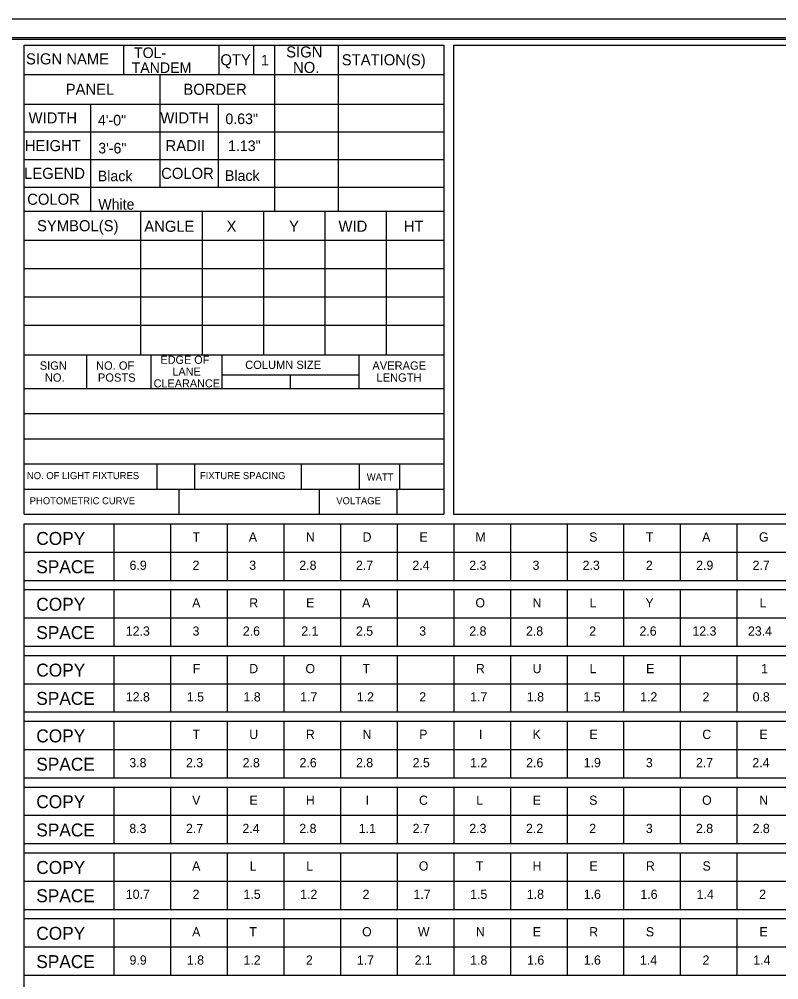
# Model space of a CAD drawing. Extents: x 17890071 to 17890754, y 17897628 to 17897992.
# Drawn here: x 17890152.1 to 17890192.5, y 17897819.5 to 17897870.5 of the extents above; entities that cross this region are included whole.
import ezdxf

# ---------------------------------------------------------------- set-up
doc = ezdxf.new("R2010")
doc.units = 0
for name, color, linetype in [('GSSign', 7, 'Continuous'), ('PlotBorder_dp', 7, 'Continuous'), ('SheetBorder_dp', 7, 'Continuous'), ('SheetLinesMisc1_dp', 7, 'Continuous'), ('SheetLinesMisc2_dp', 7, 'Continuous'), ('TextMinor', 7, 'Continuous')]:
    doc.layers.add(name, color=color, linetype=linetype)

msp = doc.modelspace()

# ---------------------------------------------------------------- linework, layer by layer
at = {"layer": 'PlotBorder_dp'}
msp.add_lwpolyline([(17890071.13, 17897766.734), (17890232.646, 17897766.734), (17890232.646, 17897870.495), (17890071.13, 17897870.495)], close=True, dxfattribs=at)
at = {"layer": 'SheetBorder_dp'}
msp.add_line((17890076.514, 17897869.516), (17890227.262, 17897869.516), dxfattribs=at)
at = {"layer": 'SheetLinesMisc1_dp'}
for p, q in [((17890157.678, 17897867.555), (17890157.678, 17897869.124)), ((17890162.725, 17897869.124), (17890162.725, 17897867.555)), ((17890164.578, 17897869.124), (17890164.578, 17897867.555)), ((17890165.682, 17897869.124), (17890165.682, 17897860.289)), ((17890169.077, 17897869.124), (17890169.077, 17897860.289)), ((17890152.384, 17897867.555), (17890174.695, 17897867.555)), ((17890159.594, 17897867.555), (17890159.594, 17897861.554)), ((17890152.384, 17897865.987), (17890174.695, 17897865.987)), ((17890155.91, 17897865.987), (17890155.91, 17897860.289)), ((17890162.706, 17897865.971), (17890162.706, 17897861.554)), ((17890152.384, 17897864.514), (17890174.695, 17897864.514)), ((17890152.384, 17897863.042), (17890174.695, 17897863.042)), ((17890152.384, 17897861.569), (17890174.695, 17897861.569)), ((17890152.384, 17897860.289), (17890174.695, 17897860.289)), ((17890158.58, 17897860.289), (17890158.58, 17897852.67)), ((17890161.84, 17897860.289), (17890161.84, 17897852.67)), ((17890165.1, 17897860.289), (17890165.1, 17897852.67)), ((17890168.36, 17897860.26), (17890168.36, 17897852.67)), ((17890171.62, 17897860.26), (17890171.62, 17897852.67)), ((17890152.389, 17897858.756), (17890174.695, 17897858.756)), ((17890152.389, 17897857.253), (17890174.695, 17897857.253)), ((17890152.389, 17897855.75), (17890174.695, 17897855.75)), ((17890152.389, 17897854.246), (17890174.695, 17897854.246)), ((17890152.384, 17897852.67), (17890174.695, 17897852.67)), ((17890155.694, 17897852.67), (17890155.694, 17897850.874)), ((17890159.117, 17897852.67), (17890159.117, 17897850.874)), ((17890162.895, 17897852.67), (17890162.895, 17897850.874)), ((17890170.171, 17897852.67), (17890170.171, 17897850.874)), ((17890162.895, 17897851.593), (17890170.166, 17897851.593)), ((17890166.53, 17897851.593), (17890166.53, 17897850.874)), ((17890152.384, 17897850.874), (17890174.694, 17897850.874)), ((17890152.384, 17897849.538), (17890174.694, 17897849.538)), ((17890152.384, 17897848.203), (17890174.695, 17897848.203)), ((17890152.384, 17897846.867), (17890174.695, 17897846.867)), ((17890152.384, 17897845.531), (17890174.695, 17897845.531)), ((17890157.148, 17897843.684), (17890157.148, 17897840.678)), ((17890160.159, 17897843.684), (17890160.159, 17897840.678)), ((17890163.169, 17897843.684), (17890163.169, 17897840.678)), ((17890166.179, 17897843.684), (17890166.179, 17897840.678)), ((17890169.19, 17897843.684), (17890169.19, 17897840.678)), ((17890172.2, 17897843.684), (17890172.2, 17897840.678)), ((17890175.211, 17897843.684), (17890175.211, 17897840.678)), ((17890178.221, 17897843.684), (17890178.221, 17897840.678)), ((17890181.231, 17897843.684), (17890181.231, 17897840.678)), ((17890184.241, 17897843.684), (17890184.241, 17897840.678)), ((17890187.252, 17897843.684), (17890187.252, 17897840.678)), ((17890190.262, 17897843.684), (17890190.262, 17897840.678)), ((17890152.385, 17897842.181), (17890226.387, 17897842.182)), ((17890152.385, 17897840.678), (17890226.387, 17897840.678)), ((17890152.385, 17897840.188), (17890226.387, 17897840.188)), ((17890157.148, 17897840.188), (17890157.148, 17897837.182)), ((17890160.159, 17897840.188), (17890160.159, 17897837.182)), ((17890163.169, 17897840.188), (17890163.169, 17897837.182)), ((17890166.179, 17897840.188), (17890166.179, 17897837.182)), ((17890169.19, 17897840.188), (17890169.19, 17897837.182)), ((17890172.2, 17897840.188), (17890172.2, 17897837.182)), ((17890175.211, 17897840.188), (17890175.211, 17897837.182)), ((17890178.221, 17897840.188), (17890178.221, 17897837.182)), ((17890181.231, 17897840.188), (17890181.231, 17897837.182)), ((17890184.241, 17897840.188), (17890184.241, 17897837.182)), ((17890187.252, 17897840.188), (17890187.252, 17897837.182)), ((17890190.262, 17897840.188), (17890190.262, 17897837.182)), ((17890152.385, 17897838.685), (17890226.387, 17897838.685)), ((17890152.385, 17897837.182), (17890226.387, 17897837.182)), ((17890152.385, 17897836.691), (17890226.387, 17897836.691)), ((17890157.148, 17897836.691), (17890157.148, 17897833.685)), ((17890160.159, 17897836.691), (17890160.159, 17897833.685)), ((17890163.169, 17897836.691), (17890163.169, 17897833.685)), ((17890166.179, 17897836.691), (17890166.179, 17897833.685)), ((17890169.19, 17897836.691), (17890169.19, 17897833.685)), ((17890172.2, 17897836.691), (17890172.2, 17897833.685)), ((17890175.211, 17897836.691), (17890175.211, 17897833.685)), ((17890178.221, 17897836.691), (17890178.221, 17897833.685)), ((17890181.231, 17897836.691), (17890181.231, 17897833.685)), ((17890184.241, 17897836.691), (17890184.241, 17897833.685)), ((17890187.252, 17897836.691), (17890187.252, 17897833.685)), ((17890190.262, 17897836.691), (17890190.262, 17897833.685)), ((17890152.385, 17897835.188), (17890226.387, 17897835.188)), ((17890152.385, 17897833.685), (17890226.387, 17897833.685)), ((17890152.385, 17897833.194), (17890226.387, 17897833.194)), ((17890157.148, 17897833.194), (17890157.148, 17897830.188)), ((17890160.159, 17897833.194), (17890160.159, 17897830.188)), ((17890163.169, 17897833.194), (17890163.169, 17897830.188)), ((17890166.179, 17897833.194), (17890166.179, 17897830.188)), ((17890169.19, 17897833.194), (17890169.19, 17897830.188)), ((17890172.2, 17897833.194), (17890172.2, 17897830.188)), ((17890175.211, 17897833.194), (17890175.211, 17897830.188)), ((17890178.221, 17897833.194), (17890178.221, 17897830.188)), ((17890181.231, 17897833.194), (17890181.231, 17897830.188)), ((17890184.241, 17897833.194), (17890184.241, 17897830.188)), ((17890187.252, 17897833.194), (17890187.252, 17897830.188)), ((17890190.262, 17897833.194), (17890190.262, 17897830.188)), ((17890152.385, 17897831.692), (17890226.387, 17897831.692)), ((17890152.385, 17897830.188), (17890226.387, 17897830.188)), ((17890152.385, 17897829.698), (17890226.387, 17897829.698)), ((17890157.148, 17897829.698), (17890157.148, 17897826.692)), ((17890160.159, 17897829.698), (17890160.159, 17897826.692)), ((17890163.169, 17897829.698), (17890163.169, 17897826.692)), ((17890166.179, 17897829.698), (17890166.179, 17897826.692)), ((17890169.19, 17897829.698), (17890169.19, 17897826.692)), ((17890172.2, 17897829.698), (17890172.2, 17897826.692)), ((17890175.211, 17897829.698), (17890175.211, 17897826.692)), ((17890178.221, 17897829.698), (17890178.221, 17897826.692)), ((17890181.231, 17897829.698), (17890181.231, 17897826.692)), ((17890184.241, 17897829.698), (17890184.241, 17897826.692)), ((17890187.252, 17897829.698), (17890187.252, 17897826.692)), ((17890190.262, 17897829.698), (17890190.262, 17897826.692)), ((17890152.385, 17897828.195), (17890226.387, 17897828.195)), ((17890152.385, 17897826.692), (17890226.387, 17897826.692)), ((17890152.385, 17897826.202), (17890226.387, 17897826.202)), ((17890157.148, 17897826.202), (17890157.148, 17897823.196)), ((17890160.159, 17897826.202), (17890160.159, 17897823.196)), ((17890163.169, 17897826.202), (17890163.169, 17897823.196)), ((17890166.179, 17897826.202), (17890166.179, 17897823.196)), ((17890169.19, 17897826.202), (17890169.19, 17897823.196)), ((17890172.2, 17897826.202), (17890172.2, 17897823.196)), ((17890175.211, 17897826.202), (17890175.211, 17897823.196)), ((17890178.221, 17897826.202), (17890178.221, 17897823.196)), ((17890181.231, 17897826.202), (17890181.231, 17897823.196)), ((17890184.241, 17897826.202), (17890184.241, 17897823.196)), ((17890187.252, 17897826.202), (17890187.252, 17897823.196)), ((17890190.262, 17897826.202), (17890190.262, 17897823.196)), ((17890152.385, 17897824.698), (17890226.387, 17897824.699)), ((17890152.385, 17897823.196), (17890226.387, 17897823.196)), ((17890152.385, 17897822.705), (17890226.387, 17897822.705)), ((17890157.148, 17897822.705), (17890157.148, 17897819.699)), ((17890160.159, 17897822.705), (17890160.159, 17897819.699)), ((17890163.169, 17897822.705), (17890163.169, 17897819.699)), ((17890166.179, 17897822.705), (17890166.179, 17897819.699)), ((17890169.19, 17897822.705), (17890169.19, 17897819.699)), ((17890172.2, 17897822.705), (17890172.2, 17897819.699)), ((17890175.211, 17897822.705), (17890175.211, 17897819.699)), ((17890178.221, 17897822.705), (17890178.221, 17897819.699)), ((17890181.231, 17897822.705), (17890181.231, 17897819.699)), ((17890184.241, 17897822.705), (17890184.241, 17897819.699)), ((17890187.252, 17897822.705), (17890187.252, 17897819.699)), ((17890190.262, 17897822.705), (17890190.262, 17897819.699)), ((17890152.385, 17897821.202), (17890226.387, 17897821.202)), ((17890152.385, 17897819.699), (17890226.387, 17897819.699))]:
    msp.add_line(p, q, dxfattribs=at)
at = {"layer": 'SheetLinesMisc2_dp'}
for p, q in [((17890076.643, 17897869.435), (17890227.099, 17897869.435)), ((17890152.384, 17897869.124), (17890174.695, 17897869.124)), ((17890152.384, 17897844.196), (17890152.384, 17897869.124)), ((17890152.384, 17897869.124), (17890174.695, 17897869.124)), ((17890174.695, 17897869.124), (17890174.695, 17897844.196)), ((17890175.208, 17897869.124), (17890226.38, 17897869.124)), ((17890175.208, 17897869.124), (17890175.208, 17897844.198)), ((17890152.384, 17897846.866), (17890174.69, 17897846.866)), ((17890159.442, 17897846.866), (17890159.442, 17897845.531)), ((17890161.435, 17897846.866), (17890161.435, 17897845.531)), ((17890167.11, 17897846.866), (17890167.11, 17897845.531)), ((17890170.196, 17897846.866), (17890170.196, 17897845.531)), ((17890172.326, 17897846.866), (17890172.326, 17897845.531)), ((17890152.384, 17897845.531), (17890174.69, 17897845.531)), ((17890160.612, 17897845.531), (17890160.612, 17897844.196)), ((17890168.055, 17897845.531), (17890168.055, 17897844.196)), ((17890172.196, 17897845.531), (17890172.196, 17897844.196)), ((17890152.384, 17897844.196), (17890174.69, 17897844.196)), ((17890152.384, 17897844.196), (17890174.695, 17897844.196)), ((17890175.208, 17897844.198), (17890226.38, 17897844.198)), ((17890152.385, 17897823.197), (17890152.385, 17897843.684)), ((17890152.385, 17897843.684), (17890226.387, 17897843.684)), ((17890152.385, 17897776.142), (17890152.385, 17897843.684))]:
    msp.add_line(p, q, dxfattribs=at)

# ---------------------------------------------------------------- texts
at = {"layer": 'GSSign'}
for s, height, p in [('TOL-', 0.5624, (17890158.225, 17897868.433)), ('1', 0.562, (17890164.974, 17897868.039)), ('TANDEM', 0.5624, (17890158.1, 17897867.637)), ('4\'-0"', 0.5624, (17890156.309, 17897864.848)), ('0.63"', 0.5624, (17890163.082, 17897864.922)), ('3\'-6"', 0.5624, (17890156.325, 17897863.363)), ('1.13"', 0.5624, (17890163.222, 17897863.488)), ('Black', 0.5624, (17890156.303, 17897861.883)), ('Black', 0.5624, (17890163.059, 17897861.904)), ('White', 0.5624, (17890156.328, 17897860.379)), ('T', 0.49, (17890161.338, 17897842.739)), ('A', 0.49, (17890164.325, 17897842.739)), ('N', 0.49, (17890167.359, 17897842.739)), ('D', 0.49, (17890170.37, 17897842.739)), ('E', 0.49, (17890173.392, 17897842.739)), ('M', 0.49, (17890176.367, 17897842.739)), ('S', 0.49, (17890182.411, 17897842.739)), ('T', 0.49, (17890185.421, 17897842.739)), ('A', 0.49, (17890188.408, 17897842.739)), ('G', 0.49, (17890191.43, 17897842.739)), ('6.9', 0.4902, (17890157.99, 17897841.236)), ('2', 0.49, (17890161.338, 17897841.236)), ('3', 0.49, (17890164.349, 17897841.236)), ('2.8', 0.4902, (17890167.009, 17897841.236)), ('2.7', 0.4902, (17890170.019, 17897841.236)), ('2.4', 0.4902, (17890173.018, 17897841.236)), ('2.3', 0.4902, (17890176.04, 17897841.236)), ('3', 0.49, (17890179.401, 17897841.236)), ('2.3', 0.4902, (17890182.061, 17897841.236)), ('2', 0.49, (17890185.421, 17897841.236)), ('2.9', 0.4902, (17890188.093, 17897841.236)), ('2.7', 0.4902, (17890191.092, 17897841.236)), ('A', 0.49, (17890161.315, 17897839.242)), ('R', 0.49, (17890164.349, 17897839.242)), ('E', 0.49, (17890167.371, 17897839.242)), ('A', 0.49, (17890170.346, 17897839.242)), ('O', 0.49, (17890176.367, 17897839.242)), ('N', 0.49, (17890179.401, 17897839.242)), ('L', 0.49, (17890182.434, 17897839.242)), ('Y', 0.49, (17890185.398, 17897839.242)), ('L', 0.49, (17890191.465, 17897839.242)), ('12.3', 0.4902, (17890157.791, 17897837.739)), ('3', 0.49, (17890161.338, 17897837.739)), ('2.6', 0.4902, (17890164.01, 17897837.739)), ('2.1', 0.4902, (17890167.114, 17897837.739)), ('2.5', 0.4902, (17890170.019, 17897837.739)), ('3', 0.49, (17890173.38, 17897837.739)), ('2.8', 0.4902, (17890176.04, 17897837.739)), ('2.8', 0.4902, (17890179.051, 17897837.739)), ('2', 0.49, (17890182.411, 17897837.739)), ('2.6', 0.4902, (17890185.083, 17897837.739)), ('12.3', 0.4902, (17890187.895, 17897837.739)), ('23.4', 0.4902, (17890190.847, 17897837.739)), ('F', 0.49, (17890161.35, 17897835.746)), ('D', 0.49, (17890164.349, 17897835.746)), ('O', 0.49, (17890167.336, 17897835.746)), ('T', 0.49, (17890170.37, 17897835.746)), ('R', 0.49, (17890176.39, 17897835.746)), ('U', 0.49, (17890179.401, 17897835.746)), ('L', 0.49, (17890182.434, 17897835.746)), ('E', 0.49, (17890185.433, 17897835.746)), ('1', 0.49, (17890191.547, 17897835.746)), ('12.8', 0.4902, (17890157.791, 17897834.243)), ('1.5', 0.4902, (17890161.035, 17897834.243)), ('1.8', 0.4902, (17890164.045, 17897834.243)), ('1.7', 0.4902, (17890167.056, 17897834.243)), ('1.2', 0.4902, (17890170.066, 17897834.243)), ('2', 0.49, (17890173.38, 17897834.243)), ('1.7', 0.4902, (17890176.087, 17897834.243)), ('1.8', 0.4902, (17890179.097, 17897834.243)), ('1.5', 0.4902, (17890182.108, 17897834.243)), ('1.2', 0.4902, (17890185.118, 17897834.243)), ('2', 0.49, (17890188.432, 17897834.243)), ('0.8', 0.4902, (17890191.092, 17897834.243)), ('T', 0.49, (17890161.338, 17897832.25)), ('U', 0.49, (17890164.349, 17897832.25)), ('R', 0.49, (17890167.359, 17897832.25)), ('N', 0.49, (17890170.37, 17897832.25)), ('P', 0.49, (17890173.38, 17897832.25)), ('I', 0.49, (17890176.554, 17897832.25)), ('K', 0.49, (17890179.401, 17897832.25)), ('E', 0.49, (17890182.423, 17897832.25)), ('C', 0.49, (17890188.42, 17897832.25)), ('E', 0.49, (17890191.454, 17897832.25)), ('3.8', 0.4902, (17890157.978, 17897830.747)), ('2.3', 0.4902, (17890160.988, 17897830.747)), ('2.8', 0.4902, (17890163.999, 17897830.747)), ('2.6', 0.4902, (17890167.021, 17897830.747)), ('2.8', 0.4902, (17890170.019, 17897830.747)), ('2.5', 0.4902, (17890173.03, 17897830.747)), ('1.2', 0.4902, (17890176.087, 17897830.747)), ('2.6', 0.4902, (17890179.062, 17897830.747)), ('1.9', 0.4902, (17890182.119, 17897830.747)), ('3', 0.49, (17890185.421, 17897830.747)), ('2.7', 0.4902, (17890188.082, 17897830.747)), ('2.4', 0.4902, (17890191.08, 17897830.747)), ('V', 0.49, (17890161.315, 17897828.753)), ('E', 0.49, (17890164.36, 17897828.753)), ('H', 0.49, (17890167.359, 17897828.753)), ('I', 0.49, (17890170.533, 17897828.753)), ('C', 0.49, (17890173.368, 17897828.753)), ('L', 0.49, (17890176.414, 17897828.753)), ('E', 0.49, (17890179.412, 17897828.753)), ('S', 0.49, (17890182.411, 17897828.753)), ('O', 0.49, (17890188.408, 17897828.753)), ('N', 0.49, (17890191.442, 17897828.753)), ('8.3', 0.4902, (17890157.978, 17897827.251)), ('2.7', 0.4902, (17890160.988, 17897827.251)), ('2.4', 0.4902, (17890163.987, 17897827.251)), ('2.8', 0.4902, (17890167.009, 17897827.251)), ('1.1', 0.4902, (17890170.171, 17897827.251)), ('2.7', 0.4902, (17890173.03, 17897827.251)), ('2.3', 0.4902, (17890176.04, 17897827.251)), ('2.2', 0.4902, (17890179.051, 17897827.251)), ('2', 0.49, (17890182.411, 17897827.251)), ('3', 0.49, (17890185.421, 17897827.251)), ('2.8', 0.4902, (17890188.082, 17897827.251)), ('2.8', 0.4902, (17890191.092, 17897827.251)), ('A', 0.49, (17890161.315, 17897825.257)), ('L', 0.49, (17890164.372, 17897825.257)), ('L', 0.49, (17890167.382, 17897825.257)), ('O', 0.49, (17890173.357, 17897825.257)), ('T', 0.49, (17890176.39, 17897825.257)), ('H', 0.49, (17890179.401, 17897825.257)), ('E', 0.49, (17890182.423, 17897825.257)), ('R', 0.49, (17890185.421, 17897825.257)), ('S', 0.49, (17890188.432, 17897825.257)), ('10.7', 0.4902, (17890157.791, 17897823.754)), ('2', 0.49, (17890161.338, 17897823.754)), ('1.5', 0.4902, (17890164.045, 17897823.754)), ('1.2', 0.4902, (17890167.056, 17897823.754)), ('2', 0.49, (17890170.37, 17897823.754)), ('1.7', 0.4902, (17890173.076, 17897823.754)), ('1.5', 0.4902, (17890176.087, 17897823.754)), ('1.8', 0.4902, (17890179.097, 17897823.754)), ('1.6', 0.4902, (17890182.119, 17897823.754)), ('1.6', 0.4902, (17890185.13, 17897823.754)), ('1.4', 0.4902, (17890188.117, 17897823.754)), ('2', 0.49, (17890191.442, 17897823.754)), ('A', 0.49, (17890161.315, 17897821.761)), ('T', 0.49, (17890164.349, 17897821.761)), ('O', 0.49, (17890170.346, 17897821.761)), ('W', 0.49, (17890173.31, 17897821.761)), ('N', 0.49, (17890176.39, 17897821.761)), ('E', 0.49, (17890179.412, 17897821.761)), ('R', 0.49, (17890182.411, 17897821.761)), ('S', 0.49, (17890185.421, 17897821.761)), ('E', 0.49, (17890191.454, 17897821.761)), ('9.9', 0.4902, (17890157.99, 17897820.258)), ('1.8', 0.4902, (17890161.035, 17897820.258)), ('1.2', 0.4902, (17890164.045, 17897820.258)), ('2', 0.49, (17890167.359, 17897820.258)), ('1.7', 0.4902, (17890170.066, 17897820.258)), ('2.1', 0.4902, (17890173.135, 17897820.258)), ('1.8', 0.4902, (17890176.087, 17897820.258)), ('1.6', 0.4902, (17890179.109, 17897820.258)), ('1.6', 0.4902, (17890182.119, 17897820.258)), ('1.4', 0.4902, (17890185.106, 17897820.258)), ('2', 0.49, (17890188.432, 17897820.258)), ('1.4', 0.4902, (17890191.127, 17897820.258))]:
    msp.add_text(s, height=height, dxfattribs=at).set_placement(p)
at = {"layer": 'TextMinor'}
for s, height, p in [('SIGN', 0.5882, (17890166.312, 17897868.463)), ('SIGN NAME', 0.5882, (17890152.487, 17897868.094)), ('QTY', 0.5882, (17890162.816, 17897868.045)), ('STATION(S)', 0.5882, (17890169.266, 17897868.045)), ('NO.', 0.5882, (17890166.675, 17897867.639)), ('PANEL', 0.5882, (17890154.597, 17897866.477)), ('BORDER', 0.5882, (17890160.851, 17897866.477)), ('WIDTH', 0.5882, (17890152.624, 17897864.956)), ('WIDTH', 0.5882, (17890159.627, 17897864.956)), ('HEIGHT', 0.5882, (17890152.427, 17897863.484)), ('RADII', 0.5882, (17890159.903, 17897863.484)), ('LEGEND', 0.5882, (17890152.386, 17897862.012)), ('COLOR', 0.5882, (17890159.667, 17897862.012)), ('COLOR', 0.5882, (17890152.552, 17897860.635)), ('SYMBOL(S)', 0.5882, (17890153.074, 17897859.229)), ('ANGLE', 0.5882, (17890158.77, 17897859.2)), ('X', 0.588, (17890163.144, 17897859.2)), ('Y', 0.588, (17890166.465, 17897859.2)), ('WID', 0.5882, (17890169.091, 17897859.2)), ('HT', 0.5882, (17890172.558, 17897859.2)), ('SIGN', 0.4411, (17890153.217, 17897851.87)), ('NO. OF', 0.4411, (17890156.209, 17897851.87)), ('EDGE OF', 0.4313, (17890159.631, 17897852.184)), ('COLUMN SIZE', 0.44113, (17890164.133, 17897851.911)), ('AVERAGE', 0.4411, (17890170.89, 17897851.87)), ('NO.', 0.4411, (17890153.489, 17897851.233)), ('POSTS', 0.4411, (17890156.309, 17897851.233)), ('LANE', 0.4313, (17890160.265, 17897851.556)), ('LENGTH', 0.4411, (17890171.108, 17897851.233)), ('CLEARANCE', 0.4313, (17890159.269, 17897850.929)), ('NO. OF LIGHT FIXTURES', 0.37485, (17890152.537, 17897846.057)), ('FIXTURE SPACING', 0.37485, (17890161.728, 17897846.057)), ('WATT', 0.3749, (17890170.594, 17897845.982)), ('PHOTOMETRIC CURVE', 0.37485, (17890152.685, 17897844.721)), ('VOLTAGE', 0.3749, (17890168.974, 17897844.721)), ('COPY', 0.6862, (17890153.034, 17897842.563)), ('SPACE', 0.6862, (17890153.034, 17897841.06)), ('COPY', 0.6862, (17890153.034, 17897839.064)), ('SPACE', 0.6862, (17890153.034, 17897837.56)), ('COPY', 0.6862, (17890153.034, 17897835.567)), ('SPACE', 0.6862, (17890153.034, 17897834.064)), ('COPY', 0.6862, (17890153.034, 17897832.07)), ('SPACE', 0.6862, (17890153.034, 17897830.566)), ('COPY', 0.6862, (17890153.034, 17897828.574)), ('SPACE', 0.6862, (17890153.034, 17897827.071)), ('COPY', 0.6862, (17890153.034, 17897825.081)), ('SPACE', 0.6862, (17890153.034, 17897823.577)), ('COPY', 0.6862, (17890153.034, 17897821.581)), ('SPACE', 0.6862, (17890153.034, 17897820.077))]:
    msp.add_text(s, height=height, dxfattribs=at).set_placement(p)

doc.saveas('drawing.dxf')
